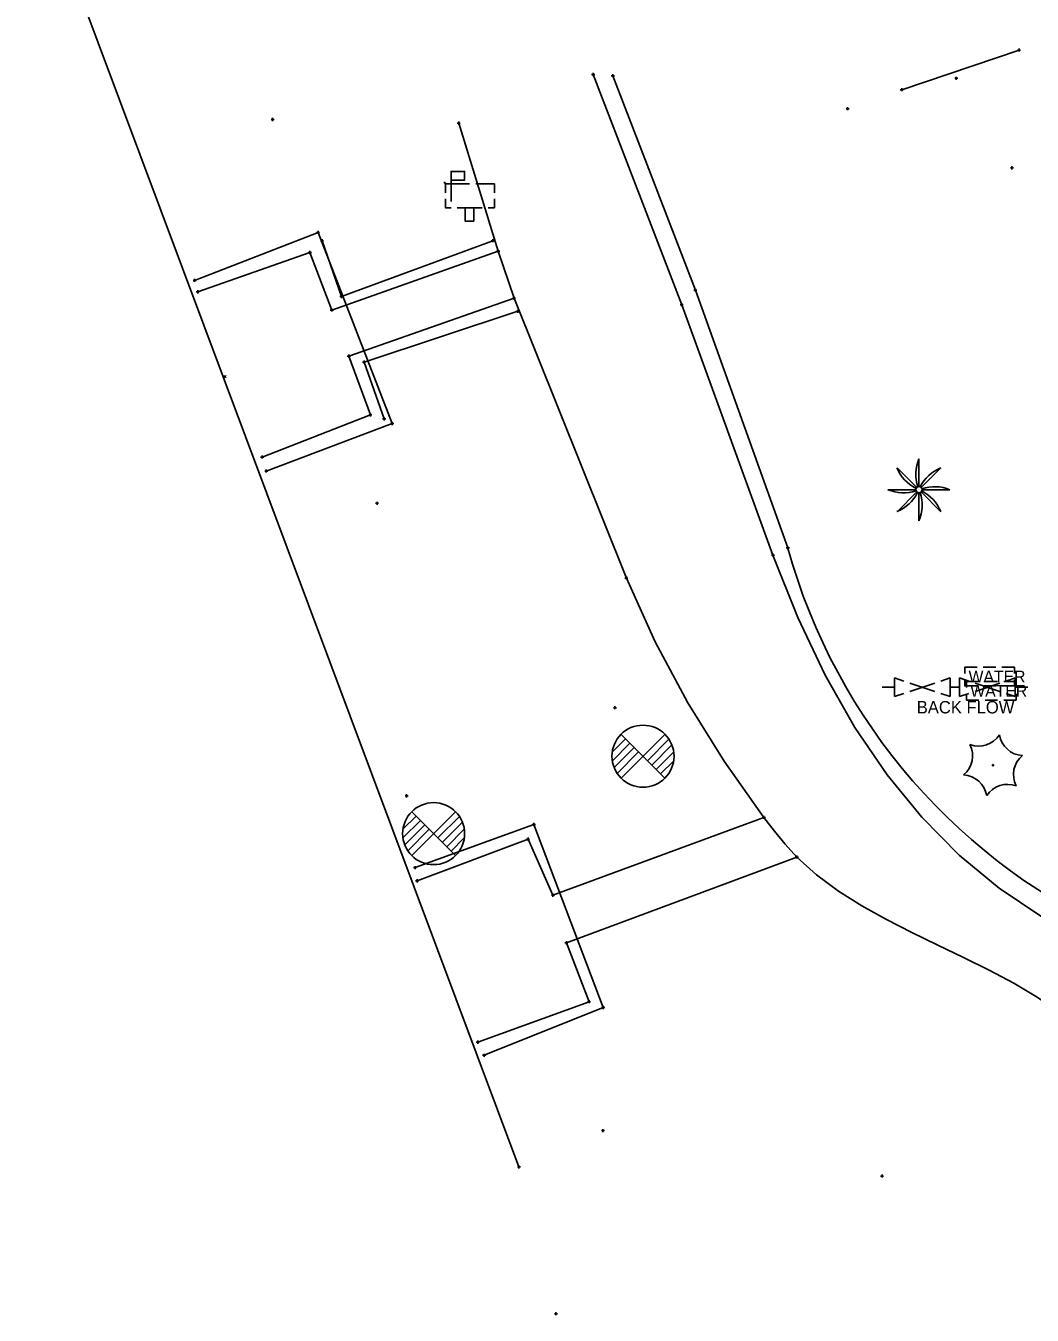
# Model space of a CAD drawing. Extents: x 1954856 to 2011933, y 399149 to 426294.
# Drawn here: x 2004840.1 to 2004921.2, y 407791.4 to 407895.4 of the extents above; entities that cross this region are included whole.
import ezdxf

# ---------------------------------------------------------------- set-up
doc = ezdxf.new("R2010")
doc.units = 0
for name, color, linetype in [('Building_ep', 7, 'Continuous'), ('BuildingOH_ep', 7, 'Continuous'), ('Driveway_ep', 7, 'Continuous'), ('FFElev_ep', 7, 'Continuous'), ('Mailbox_ep', 7, 'Continuous'), ('MeterWater_ep', 7, 'Continuous'), ('PointLocator_ep', 7, 'Continuous'), ('ShrubHedge_ep', 7, 'Continuous'), ('SidewalkFront_ep', 7, 'Continuous'), ('SignMulti_ep', 7, 'Continuous'), ('TreePalm_ep', 7, 'Continuous'), ('TreePine_ep', 7, 'Continuous'), ('ValveBFP_ep', 7, 'Continuous'), ('XSPt_ep', 7, 'Continuous')]:
    doc.layers.add(name, color=color, linetype=linetype)

msp = doc.modelspace()

# ---------------------------------------------------------------- linework, layer by layer
at = {"layer": 'Building_ep'}
msp.add_lwpolyline([(2004879.86, 407803.38), (2004840.86, 407907.59), (2004866.81, 407917.3), (2004840.1, 407988.66), (2004861.17, 407996.55)], dxfattribs=at)
at = {"layer": 'BuildingOH_ep'}
for points in [[(2004859.48, 407859.48), (2004869.64, 407863.31), (2004863.67, 407878.72), (2004853.7, 407874.85)], [(2004877.06, 407812.39), (2004886.65, 407816.24), (2004881.05, 407830.99), (2004871.49, 407827.51)]]:
    msp.add_lwpolyline(points, dxfattribs=at)
at = {"layer": 'Driveway_ep'}
for p, q in [((2004892.98, 407872.89), (2004885.85, 407891.45)), ((2004875, 407887.52), (2004878.19, 407877.21)), ((2004878.19, 407877.21), (2004879.46, 407873.41)), ((2004879.46, 407873.41), (2004888.53, 407850.85)), ((2004900.34, 407852.71), (2004892.98, 407872.89))]:
    msp.add_line(p, q, dxfattribs=at)
for points in [[(2004922.01, 407823.53), (2004918.57, 407825.85), (2004915.35, 407828.52), (2004912.34, 407831.57), (2004909.54, 407835), (2004906.95, 407838.81), (2004904.55, 407843.03), (2004902.35, 407847.66), (2004900.34, 407852.71)], [(2004888.53, 407850.85), (2004890.83, 407845.71), (2004893.47, 407840.8), (2004896.41, 407836.09), (2004899.61, 407831.56), (2004900.45, 407830.46), (2004901.33, 407829.39), (2004902.27, 407828.36), (2004903.85, 407826.92), (2004905.61, 407825.62), (2004907.5, 407824.43), (2004909.48, 407823.32), (2004911.54, 407822.27), (2004913.62, 407821.26), (2004915.71, 407820.26), (2004917.77, 407819.24), (2004919.75, 407818.19), (2004921.64, 407817.07), (2004923.4, 407815.86), (2004924.99, 407814.53), (2004926.38, 407813.06), (2004927.54, 407811.43), (2004928.44, 407809.61), (2004929.04, 407807.57)]]:
    msp.add_lwpolyline(points, dxfattribs=at)
at = {"layer": 'FFElev_ep'}
for p, q in [((2004856.24, 407866.99), (2004856.06, 407867.17)), ((2004856.24, 407867.17), (2004856.06, 407866.99)), ((2004856.15, 407867.08), (2004856.15, 407867.08))]:
    msp.add_line(p, q, dxfattribs=at)
at = {"layer": 'Mailbox_ep'}
for p, q in [((2004873.93, 407882.62), (2004873.93, 407881.91)), ((2004875.88, 407882.62), (2004873.93, 407882.62)), ((2004874.39, 407881.2), (2004874.39, 407882.94)), ((2004874.39, 407882.94), (2004875.38, 407882.94)), ((2004877.88, 407882.62), (2004877.88, 407881.91)), ((2004874.88, 407880.71), (2004875.38, 407880.71)), ((2004875.38, 407880.71), (2004876.88, 407880.71)), ((2004877.88, 407881.41), (2004877.88, 407880.71)), ((2004875.86, 407879.63), (2004875.86, 407879.63))]:
    msp.add_line(p, q, dxfattribs=at)
for points in [[(2004875.38, 407883.63), (2004874.39, 407883.63), (2004874.39, 407882.94)], [(2004875.38, 407882.94), (2004875.47, 407882.94), (2004875.47, 407883.63), (2004875.38, 407883.63)], [(2004873.81, 407882.75), (2004873.89, 407882.75), (2004873.93, 407882.57)], [(2004877.88, 407882.16), (2004877.88, 407882.62), (2004876.38, 407882.62)], [(2004873.93, 407881.41), (2004873.93, 407880.71), (2004874.38, 407880.71)], [(2004875.52, 407880.71), (2004875.52, 407879.63), (2004876.21, 407879.63), (2004876.21, 407880.71)], [(2004877.38, 407880.71), (2004877.88, 407880.71), (2004877.88, 407881.16)]]:
    msp.add_lwpolyline(points, dxfattribs=at)
at = {"layer": 'MeterWater_ep'}
for p, q in [((2004917.8, 407842.91), (2004917.8, 407842.91)), ((2004917.94, 407841.77), (2004917.94, 407841.77))]:
    msp.add_line(p, q, dxfattribs=at)
for points in [[(2004915.8, 407843.16), (2004915.8, 407843.66), (2004916.8, 407843.66)], [(2004917.3, 407843.66), (2004918.3, 407843.66)], [(2004918.8, 407843.66), (2004919.8, 407843.66), (2004919.8, 407843.16)], [(2004916.8, 407842.16), (2004915.8, 407842.16), (2004915.8, 407842.66)], [(2004915.94, 407842.02), (2004915.94, 407842.52), (2004916.94, 407842.52)], [(2004918.3, 407842.16), (2004917.3, 407842.16)], [(2004917.44, 407842.52), (2004918.44, 407842.52)], [(2004919.8, 407842.66), (2004919.8, 407842.16), (2004918.8, 407842.16)], [(2004918.94, 407842.52), (2004919.94, 407842.52), (2004919.94, 407842.02)], [(2004916.94, 407841.02), (2004915.94, 407841.02), (2004915.94, 407841.52)], [(2004918.44, 407841.02), (2004917.44, 407841.02)], [(2004919.94, 407841.52), (2004919.94, 407841.02), (2004918.94, 407841.02)]]:
    msp.add_lwpolyline(points, dxfattribs=at)
at = {"layer": 'PointLocator_ep'}
for p, q in [((2004920.31, 407893.42), (2004920.06, 407893.42)), ((2004920.18, 407893.3), (2004920.18, 407893.55)), ((2004920.18, 407893.42), (2004920.18, 407893.42)), ((2004885.97, 407891.45), (2004885.72, 407891.45)), ((2004885.85, 407891.32), (2004885.85, 407891.57)), ((2004885.85, 407891.45), (2004885.85, 407891.45)), ((2004887.55, 407891.35), (2004887.3, 407891.35)), ((2004887.42, 407891.22), (2004887.42, 407891.47)), ((2004887.42, 407891.35), (2004887.42, 407891.35)), ((2004915.24, 407891.15), (2004914.99, 407891.15)), ((2004915.12, 407891.02), (2004915.12, 407891.27)), ((2004915.12, 407891.15), (2004915.12, 407891.15)), ((2004910.85, 407890.21), (2004910.6, 407890.21)), ((2004910.72, 407890.09), (2004910.72, 407890.34)), ((2004910.72, 407890.21), (2004910.72, 407890.21)), ((2004906.36, 407888.56), (2004906.36, 407888.81)), ((2004860.12, 407887.82), (2004859.87, 407887.82)), ((2004860, 407887.69), (2004860, 407887.94)), ((2004860, 407887.82), (2004860, 407887.82)), ((2004906.49, 407888.69), (2004906.24, 407888.69)), ((2004906.36, 407888.69), (2004906.36, 407888.69)), ((2004875.13, 407887.52), (2004874.88, 407887.52)), ((2004875, 407887.4), (2004875, 407887.65)), ((2004875, 407887.52), (2004875, 407887.52)), ((2004919.74, 407883.92), (2004919.49, 407883.92)), ((2004919.61, 407883.8), (2004919.61, 407884.05)), ((2004919.61, 407883.92), (2004919.61, 407883.92)), ((2004863.79, 407878.72), (2004863.54, 407878.72)), ((2004863.67, 407878.6), (2004863.67, 407878.85)), ((2004863.67, 407878.72), (2004863.67, 407878.72)), ((2004864.1, 407878.05), (2004863.85, 407878.05)), ((2004863.98, 407877.93), (2004863.98, 407878.18)), ((2004863.98, 407878.05), (2004863.98, 407878.05)), ((2004877.88, 407878.04), (2004877.63, 407878.04)), ((2004877.75, 407877.92), (2004877.75, 407878.17)), ((2004877.75, 407878.04), (2004877.75, 407878.04)), ((2004878.19, 407877.08), (2004878.19, 407877.33)), ((2004863.12, 407877.09), (2004862.87, 407877.09)), ((2004862.99, 407876.97), (2004862.99, 407877.22)), ((2004862.99, 407877.09), (2004862.99, 407877.09)), ((2004878.31, 407877.21), (2004878.06, 407877.21)), ((2004878.19, 407877.21), (2004878.19, 407877.21)), ((2004853.83, 407874.85), (2004853.58, 407874.85)), ((2004853.7, 407874.72), (2004853.7, 407874.97)), ((2004853.7, 407874.85), (2004853.7, 407874.85)), ((2004854.08, 407873.92), (2004853.83, 407873.92)), ((2004853.96, 407873.8), (2004853.96, 407874.05)), ((2004853.96, 407873.92), (2004853.96, 407873.92)), ((2004865.68, 407873.55), (2004865.43, 407873.55)), ((2004865.56, 407873.42), (2004865.56, 407873.67)), ((2004865.56, 407873.55), (2004865.56, 407873.55)), ((2004879.58, 407873.41), (2004879.33, 407873.41)), ((2004879.46, 407873.28), (2004879.46, 407873.53)), ((2004879.46, 407873.41), (2004879.46, 407873.41)), ((2004894.21, 407874.05), (2004893.96, 407874.05)), ((2004894.08, 407873.92), (2004894.08, 407874.17)), ((2004894.08, 407874.05), (2004894.08, 407874.05)), ((2004864.9, 407872.46), (2004864.65, 407872.46)), ((2004864.77, 407872.34), (2004864.77, 407872.59)), ((2004864.77, 407872.46), (2004864.77, 407872.46)), ((2004879.9, 407872.36), (2004879.65, 407872.36)), ((2004879.77, 407872.23), (2004879.77, 407872.48)), ((2004879.77, 407872.36), (2004879.77, 407872.36)), ((2004893.11, 407872.89), (2004892.86, 407872.89)), ((2004892.98, 407872.76), (2004892.98, 407873.01)), ((2004892.98, 407872.89), (2004892.98, 407872.89)), ((2004866.27, 407868.75), (2004866.02, 407868.75)), ((2004866.15, 407868.62), (2004866.15, 407868.87)), ((2004866.15, 407868.75), (2004866.15, 407868.75)), ((2004867.49, 407868.25), (2004867.24, 407868.25)), ((2004867.37, 407868.13), (2004867.37, 407868.38)), ((2004867.37, 407868.25), (2004867.37, 407868.25)), ((2004868, 407864), (2004867.75, 407864)), ((2004867.88, 407863.87), (2004867.88, 407864.12)), ((2004867.88, 407864), (2004867.88, 407864)), ((2004869, 407863.55), (2004869, 407863.8)), ((2004869.12, 407863.68), (2004868.87, 407863.68)), ((2004869, 407863.68), (2004869, 407863.68)), ((2004869.77, 407863.31), (2004869.52, 407863.31)), ((2004869.64, 407863.18), (2004869.64, 407863.43)), ((2004869.64, 407863.31), (2004869.64, 407863.31)), ((2004859.16, 407860.49), (2004859.16, 407860.74)), ((2004859.28, 407860.61), (2004859.03, 407860.61)), ((2004859.16, 407860.61), (2004859.16, 407860.61)), ((2004859.61, 407859.48), (2004859.36, 407859.48)), ((2004859.48, 407859.35), (2004859.48, 407859.6)), ((2004859.48, 407859.48), (2004859.48, 407859.48)), ((2004868.54, 407856.88), (2004868.29, 407856.88)), ((2004868.42, 407856.75), (2004868.42, 407857)), ((2004868.42, 407856.88), (2004868.42, 407856.88)), ((2004901.54, 407853.15), (2004901.54, 407853.4)), ((2004900.46, 407852.71), (2004900.21, 407852.71)), ((2004900.34, 407852.59), (2004900.34, 407852.84)), ((2004900.34, 407852.71), (2004900.34, 407852.71)), ((2004901.66, 407853.28), (2004901.41, 407853.28)), ((2004901.54, 407853.28), (2004901.54, 407853.28)), ((2004888.65, 407850.85), (2004888.4, 407850.85)), ((2004888.53, 407850.73), (2004888.53, 407850.98)), ((2004888.53, 407850.85), (2004888.53, 407850.85)), ((2004887.72, 407840.4), (2004887.47, 407840.4)), ((2004887.6, 407840.28), (2004887.6, 407840.53)), ((2004887.6, 407840.4), (2004887.6, 407840.4)), ((2004870.93, 407833.29), (2004870.68, 407833.29)), ((2004870.8, 407833.17), (2004870.8, 407833.42)), ((2004870.8, 407833.29), (2004870.8, 407833.29)), ((2004899.74, 407831.56), (2004899.49, 407831.56)), ((2004899.61, 407831.44), (2004899.61, 407831.69)), ((2004899.61, 407831.56), (2004899.61, 407831.56)), ((2004881.18, 407830.99), (2004880.93, 407830.99)), ((2004881.05, 407830.86), (2004881.05, 407831.11)), ((2004881.05, 407830.99), (2004881.05, 407830.99)), ((2004880.71, 407829.81), (2004880.46, 407829.81)), ((2004880.59, 407829.68), (2004880.59, 407829.93)), ((2004880.59, 407829.81), (2004880.59, 407829.81)), ((2004902.27, 407828.24), (2004902.27, 407828.49)), ((2004871.61, 407827.51), (2004871.36, 407827.51)), ((2004871.49, 407827.39), (2004871.49, 407827.64)), ((2004871.49, 407827.51), (2004871.49, 407827.51)), ((2004902.39, 407828.36), (2004902.14, 407828.36)), ((2004902.27, 407828.36), (2004902.27, 407828.36)), ((2004871.78, 407826.45), (2004871.53, 407826.45)), ((2004871.66, 407826.32), (2004871.66, 407826.57)), ((2004871.66, 407826.45), (2004871.66, 407826.45)), ((2004882.59, 407825.16), (2004882.59, 407825.41)), ((2004882.72, 407825.28), (2004882.47, 407825.28)), ((2004882.59, 407825.28), (2004882.59, 407825.28)), ((2004883.81, 407821.44), (2004883.56, 407821.44)), ((2004883.68, 407821.32), (2004883.68, 407821.57)), ((2004883.68, 407821.44), (2004883.68, 407821.44)), ((2004885.63, 407816.7), (2004885.38, 407816.7)), ((2004885.51, 407816.57), (2004885.51, 407816.82)), ((2004885.51, 407816.7), (2004885.51, 407816.7)), ((2004886.78, 407816.24), (2004886.53, 407816.24)), ((2004886.65, 407816.11), (2004886.65, 407816.36)), ((2004886.65, 407816.24), (2004886.65, 407816.24)), ((2004876.66, 407813.44), (2004876.41, 407813.44)), ((2004876.54, 407813.31), (2004876.54, 407813.56)), ((2004876.54, 407813.44), (2004876.54, 407813.44)), ((2004877.18, 407812.39), (2004876.93, 407812.39)), ((2004877.06, 407812.26), (2004877.06, 407812.51)), ((2004877.06, 407812.39), (2004877.06, 407812.39)), ((2004886.76, 407806.31), (2004886.51, 407806.31)), ((2004886.63, 407806.18), (2004886.63, 407806.43)), ((2004886.63, 407806.31), (2004886.63, 407806.31)), ((2004879.86, 407803.26), (2004879.86, 407803.51)), ((2004879.99, 407803.38), (2004879.74, 407803.38)), ((2004879.86, 407803.38), (2004879.86, 407803.38)), ((2004909.26, 407802.64), (2004909.01, 407802.64)), ((2004909.13, 407802.52), (2004909.13, 407802.77)), ((2004909.13, 407802.64), (2004909.13, 407802.64)), ((2004882.97, 407791.55), (2004882.72, 407791.55)), ((2004882.84, 407791.43), (2004882.84, 407791.68)), ((2004882.84, 407791.55), (2004882.84, 407791.55))]:
    msp.add_line(p, q, dxfattribs=at)
at = {"layer": 'ShrubHedge_ep'}
for p, q in [((2004894.08, 407874.05), (2004887.42, 407891.35)), ((2004901.54, 407853.28), (2004894.08, 407874.05))]:
    msp.add_line(p, q, dxfattribs=at)
for points in [[(2004863.98, 407878.05), (2004865.56, 407873.55), (2004877.75, 407878.04)], [(2004879.77, 407872.36), (2004867.37, 407868.25), (2004869, 407863.68)]]:
    msp.add_lwpolyline(points, dxfattribs=at)
msp.add_arc((2004947.96, 407866.11), 48.17, 195.4539, 297.7964, dxfattribs=at)
at = {"layer": 'SidewalkFront_ep'}
for points in [[(2004853.96, 407873.92), (2004862.99, 407877.09), (2004864.77, 407872.46), (2004878.19, 407877.21)], [(2004879.46, 407873.41), (2004866.15, 407868.75), (2004867.88, 407864), (2004859.16, 407860.61)], [(2004871.66, 407826.45), (2004880.59, 407829.81), (2004882.59, 407825.28), (2004899.61, 407831.56)], [(2004902.27, 407828.36), (2004883.68, 407821.44), (2004885.51, 407816.7), (2004876.54, 407813.44)]]:
    msp.add_lwpolyline(points, dxfattribs=at)
at = {"layer": 'SignMulti_ep'}
msp.add_lwpolyline([(2004910.72, 407890.21), (2004920.18, 407893.42)], dxfattribs=at)
at = {"layer": 'TreePalm_ep'}
for p, q in [((2004911.93, 407858.15), (2004910.34, 407859.74)), ((2004912.11, 407858.22), (2004912.11, 407860.47)), ((2004912.28, 407858.15), (2004913.87, 407859.74)), ((2004909.61, 407857.97), (2004911.86, 407857.97)), ((2004910.34, 407856.2), (2004911.93, 407857.79)), ((2004912.11, 407857.97), (2004912.11, 407857.97)), ((2004912.11, 407855.47), (2004912.11, 407857.72)), ((2004913.87, 407856.2), (2004912.28, 407857.79)), ((2004912.36, 407857.97), (2004914.61, 407857.97))]:
    msp.add_line(p, q, dxfattribs=at)
msp.add_circle((2004912.11, 407857.97), 0.25, dxfattribs=at)
for centre, start, end in [((2004913.34, 407860.98), 202.3801, 243.2114), ((2004915.11, 407859.22), 157.3801, 198.2114), ((2004915.11, 407856.73), 112.3801, 153.2114), ((2004910.86, 407860.97), 247.3801, 288.2114), ((2004909.1, 407859.21), 292.3801, 333.2114), ((2004909.11, 407856.72), 337.3801, 18.2114), ((2004910.87, 407854.97), 22.3801, 63.2114), ((2004913.36, 407854.97), 67.3801, 108.2114)]:
    msp.add_arc(centre, 3.25, start, end, dxfattribs=at)
at = {"layer": 'TreePine_ep'}
msp.add_line((2004918.08, 407835.76), (2004918.08, 407835.76), dxfattribs=at)
msp.add_circle((2004918.08, 407835.76), 0.05, dxfattribs=at)
for centre, start, end in [((2004916.92, 407839.3), 249.5678, 326.9322), ((2004920.57, 407838.54), 189.5678, 266.9322), ((2004914.44, 407836.52), 309.5678, 26.9322), ((2004921.73, 407835), 129.5678, 206.9322), ((2004915.6, 407832.98), 9.5678, 86.9322), ((2004919.25, 407832.22), 69.5678, 146.9322)]:
    msp.add_arc(centre, 2, start, end, dxfattribs=at)
at = {"layer": 'ValveBFP_ep'}
for p, q in [((2004909.13, 407842.05), (2004910.13, 407842.05)), ((2004910.13, 407841.3), (2004910.13, 407842.8)), ((2004910.88, 407842.55), (2004910.13, 407842.8)), ((2004911.38, 407841.72), (2004913.38, 407842.38)), ((2004913.38, 407841.72), (2004911.38, 407842.38)), ((2004913.88, 407842.55), (2004914.63, 407842.8)), ((2004914.63, 407842.8), (2004914.63, 407841.3)), ((2004914.63, 407842.05), (2004915.38, 407842.05)), ((2004915, 407842.05), (2004915, 407842.05)), ((2004915.38, 407841.3), (2004915.38, 407842.8)), ((2004916.13, 407842.55), (2004915.38, 407842.8)), ((2004916.63, 407841.72), (2004918.63, 407842.38)), ((2004918.63, 407841.72), (2004916.63, 407842.38)), ((2004919.13, 407842.55), (2004919.88, 407842.8)), ((2004919.88, 407842.8), (2004919.88, 407841.3)), ((2004919.88, 407842.05), (2004920.88, 407842.05)), ((2004910.13, 407841.3), (2004910.88, 407841.55)), ((2004914.63, 407841.3), (2004913.88, 407841.55)), ((2004915.38, 407841.3), (2004916.13, 407841.55)), ((2004919.88, 407841.3), (2004919.13, 407841.55))]:
    msp.add_line(p, q, dxfattribs=at)
at = {"layer": 'XSPt_ep'}
for p, q in [((2004887.39, 407836.84), (2004888.45, 407837.9)), ((2004888.09, 407834.72), (2004891.63, 407838.25)), ((2004891.63, 407834.72), (2004888.09, 407838.25)), ((2004890.21, 407836.13), (2004891.95, 407837.87)), ((2004887.39, 407836.13), (2004888.8, 407837.55)), ((2004887.53, 407835.57), (2004889.15, 407837.19)), ((2004887.78, 407835.11), (2004889.51, 407836.84)), ((2004890.57, 407835.78), (2004892.19, 407837.4)), ((2004890.92, 407835.43), (2004892.34, 407836.84)), ((2004889.86, 407836.49), (2004889.86, 407836.49)), ((2004891.28, 407835.07), (2004892.34, 407836.13)), ((2004870.5, 407830.61), (2004871.56, 407831.67)), ((2004871.21, 407828.48), (2004874.74, 407832.02)), ((2004874.74, 407828.48), (2004871.21, 407832.02)), ((2004873.33, 407829.9), (2004875.06, 407831.63)), ((2004870.5, 407829.9), (2004871.91, 407831.31)), ((2004870.65, 407829.34), (2004872.27, 407830.96)), ((2004870.89, 407828.87), (2004872.62, 407830.61)), ((2004873.68, 407829.54), (2004875.3, 407831.17)), ((2004874.04, 407829.19), (2004875.45, 407830.61)), ((2004872.98, 407830.25), (2004872.98, 407830.25)), ((2004874.39, 407828.84), (2004875.45, 407829.9))]:
    msp.add_line(p, q, dxfattribs=at)
for centre in [(2004889.86, 407836.49), (2004872.98, 407830.25)]:
    msp.add_circle(centre, 2.5, dxfattribs=at)

# ---------------------------------------------------------------- texts
at = {"layer": 'MeterWater_ep'}
for p in [(2004916.11, 407842.44), (2004916.25, 407841.29)]:
    msp.add_text('WATER', height=0.95, dxfattribs=at).set_placement(p)
at = {"layer": 'ValveBFP_ep'}
msp.add_text('BACK FLOW', height=1, dxfattribs=at).set_placement((2004911.93, 407839.94))

doc.saveas('drawing.dxf')
